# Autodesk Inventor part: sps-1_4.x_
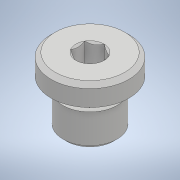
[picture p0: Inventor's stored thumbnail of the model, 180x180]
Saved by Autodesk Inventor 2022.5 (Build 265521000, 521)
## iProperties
Created: 2018-04
Part Number: sps-1_4.x_
Material: 一般
Document SubType Name: Modeling
Designer: imaocorp
Density: 1 g/cm^3
Appearance: 既定
Sending System: SOLIDWORKS 2016-2016286
MC: AMD64
MC_MODEL: AMD64 Family 21 Model 2 Stepping 0, AuthenticAMD
OS: Windows_NT
FRU: Parasolid Version 28.0, build 224,  7-29-2016
FORMAT: text
GUISE: transmit
KEY: sps-1_4
FILE: sps-1_4.x_t
DATE: Wed Apr 25 10:16:11 2018
Author: imaocorp
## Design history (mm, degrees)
feature "Base1"
node "ソリッド1"
